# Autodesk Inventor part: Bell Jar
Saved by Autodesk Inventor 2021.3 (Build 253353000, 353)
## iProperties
Created: 2022-09
Part Number: Bell Jar
Material: Generic
Document SubType Name: Modeling
Designer: Administrator
Density: 1 g/cm^3
Appearance: Default
Title: Bell Jar v7
Author: Administrator
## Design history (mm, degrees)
feature "Bell Jar" [Body]
feature "Socket Body" [Body]
feature "Shade Ring" [Body]
feature "Shade Ring +Collar" [Body]
feature "Socket" [Body]
feature "Body1"
feature "Metal Strain Relief" [Body]
feature "Fabric Cord (1)" [Body]
feature "Stem (Threaded)" [Body]
feature "Cap (Threaded)" [Body]
feature "T8-Bulb" [Body]
body "Solid1"
body "Solid2"
body "Solid3"
body "Solid4"
body "Solid5"
body "Solid6"
body "Solid7"
body "Solid8"
body "Solid9"
body "Solid10"
body "Solid11"
